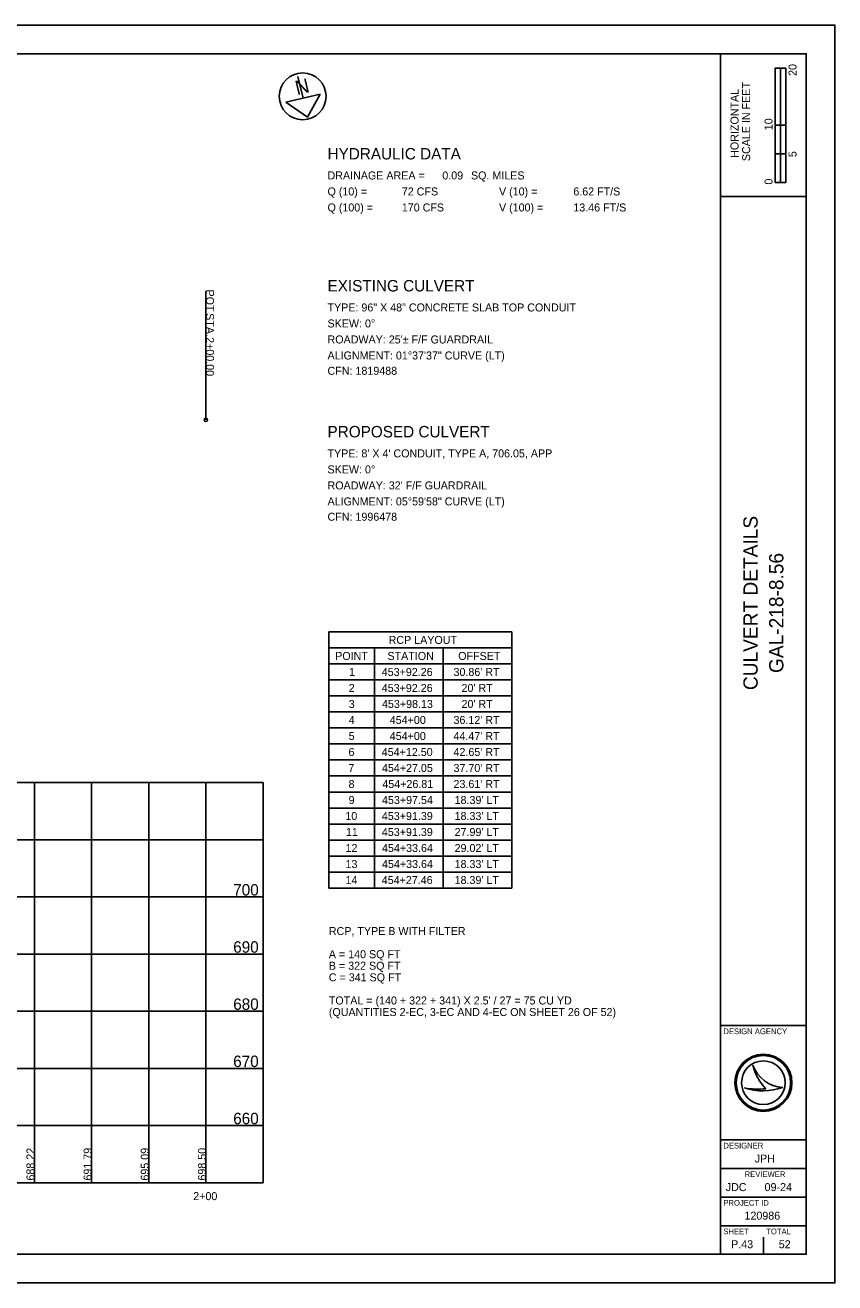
# Model space of a CAD drawing. Extents: x -1270 to 3371, y -118 to 220.
# Drawn here: x 198.4 to 340, y 0 to 220 of the extents above; entities that cross this region are included whole.
import ezdxf

# ---------------------------------------------------------------- set-up
doc = ezdxf.new("R2010")
doc.units = 0
for name, color, linetype in [('DR_P_Culvert', 7, 'Continuous'), ('DR_X_Culvert', 7, 'Continuous'), ('GE_P_Alignment', 7, 'Continuous'), ('GE_P_Alignment_100_Cardinal_Points', 7, 'Continuous'), ('GE_P_Alignment_100_Curve_Data', 7, 'Continuous'), ('PF_X_Ground_Line', 7, 'Continuous'), ('SC_Scratch1', 7, 'Continuous'), ('TX_P_1', 7, 'Continuous'), ('TX_X_1', 7, 'Continuous')]:
    doc.layers.add(name, color=color, linetype=linetype)

msp = doc.modelspace()

# ---------------------------------------------------------------- linework, layer by layer
at = {"layer": 'DR_P_Culvert'}
msp.add_line((229.98, 150.96), (229.98, 173.46), dxfattribs=at)
msp.add_circle((229.98, 150.96), 0.3, dxfattribs=at)
at = {"layer": 'DR_X_Culvert'}
msp.add_lwpolyline([(0, 0), (340, 0), (340, 220), (0, 220)], close=True, dxfattribs=at)
at = {"layer": 'GE_P_Alignment_100_Cardinal_Points'}
msp.add_circle((246.9, 207.55), 4.1, dxfattribs=at)
at = {"layer": 'GE_P_Alignment_100_Curve_Data'}
for p, q in [((246.97, 207.24), (246.07, 211)), ((249.96, 207.95), (243.98, 206.52)), ((247.77, 203.92), (249.96, 207.95)), ((243.98, 206.52), (247.77, 203.92))]:
    msp.add_line(p, q, dxfattribs=at)
msp.add_circle((246.9, 207.55), 4.1, dxfattribs=at)
at = {"layer": 'PF_X_Ground_Line'}
for p, q in [((199.98, 17.5), (199.98, 87.5)), ((209.98, 17.5), (209.98, 87.5)), ((219.98, 17.5), (219.98, 87.5)), ((229.98, 17.5), (229.98, 87.5)), ((19.98, 77.5), (239.98, 77.5)), ((19.98, 67.5), (239.98, 67.5)), ((19.98, 57.5), (239.98, 57.5)), ((19.98, 47.5), (239.98, 47.5)), ((19.98, 37.5), (239.98, 37.5)), ((19.98, 27.5), (239.98, 27.5))]:
    msp.add_line(p, q, dxfattribs=at)
at = {"layer": 'SC_Scratch1'}
for p, q in [((329.57, 192.5), (329.57, 212.5)), ((331.44, 212.5), (329.57, 212.5)), ((329.57, 202.5), (329.57, 212.5)), ((329.57, 212.5), (330.5, 212.5)), ((330.5, 212.5), (330.51, 212.5)), ((330.51, 212.5), (330.51, 202.5)), ((331.44, 212.5), (331.44, 192.5)), ((330.51, 202.5), (329.57, 202.5)), ((331.43, 202.5), (330.5, 202.5)), ((330.5, 202.5), (330.5, 197.5)), ((331.43, 197.5), (331.43, 202.5)), ((330.5, 197.5), (329.57, 197.5)), ((329.57, 197.5), (329.57, 192.5)), ((330.5, 192.5), (330.5, 197.5)), ((330.5, 197.5), (331.43, 197.5)), ((331.44, 192.5), (329.57, 192.5)), ((329.57, 192.5), (330.5, 192.5)), ((239.98, 87.5), (19.98, 87.5)), ((239.98, 17.5), (239.98, 87.5)), ((325.67, 38.1), (325.67, 38.1)), ((324.17, 34.1), (324.17, 34.1)), ((327.5, 35), (327.5, 35)), ((330.87, 34.19), (330.87, 34.19)), ((19.98, 17.5), (239.98, 17.5)), ((323.75, 6.75), (323.75, 6.75)), ((327.5, 5), (327.5, 8))]:
    msp.add_line(p, q, dxfattribs=at)
for radius in [5, 4.77, 4.77, 3.82]:
    msp.add_circle((327.5, 35), radius, dxfattribs=at)
for centre, radius, start, end in [((331.16, 39.98), 5.8, 198.9257, 198.9319), ((333.47, 39.7), 7.96, 191.6379, 191.6421), ((331.16, 39.98), 5.8, 198.9319, 267.1657), ((333.47, 39.7), 7.96, 191.6421, 226.0947), ((327.39, 43.7), 10.13, 251.4576, 290.0832), ((326.48, 46.54), 12.66, 259.4964, 259.4995), ((327.39, 43.7), 10.13, 251.4527, 251.4576), ((326.48, 46.54), 12.66, 259.4995, 276.6672)]:
    msp.add_arc(centre, radius, start, end, dxfattribs=at)
at = {"layer": 'TX_P_1'}
for p, q in [((251.48, 113.86), (283.48, 113.86)), ((251.48, 69.06), (251.48, 113.86)), ((283.48, 69.06), (283.48, 113.86)), ((251.48, 111.06), (283.48, 111.06)), ((259.48, 69.06), (259.48, 111.06)), ((271.48, 69.06), (271.48, 111.06)), ((251.48, 108.26), (283.48, 108.26)), ((251.48, 105.46), (283.48, 105.46)), ((251.48, 102.66), (283.48, 102.66)), ((251.48, 99.86), (283.48, 99.86)), ((251.48, 97.06), (283.48, 97.06)), ((251.48, 94.26), (283.48, 94.26)), ((251.48, 91.46), (283.48, 91.46)), ((251.48, 88.66), (283.48, 88.66)), ((251.48, 85.86), (283.48, 85.86)), ((251.48, 83.06), (283.48, 83.06)), ((251.48, 80.26), (283.48, 80.26)), ((251.48, 77.46), (283.48, 77.46)), ((251.48, 74.66), (283.48, 74.66)), ((251.48, 71.86), (283.48, 71.86)), ((251.48, 69.06), (283.48, 69.06))]:
    msp.add_line(p, q, dxfattribs=at)
at = {"layer": 'TX_X_1'}
for p, q in [((320, 5), (320, 215)), ((320, 190), (335, 190)), ((320, 45), (335, 45)), ((320, 25), (335, 25)), ((320, 20), (335, 20)), ((320, 15), (335, 15)), ((320, 10), (335, 10))]:
    msp.add_line(p, q, dxfattribs=at)
msp.add_lwpolyline([(15, 215), (335, 215), (335, 5), (15, 5)], close=True, dxfattribs=at)

# ---------------------------------------------------------------- texts
at = {"layer": 'DR_P_Culvert'}
for s, p in [('POT', (230, 173.75)), (' STA. ', (230, 170.14)), ('2+00.00', (230, 165.42))]:
    msp.add_text(s, height=1.4, rotation=270, dxfattribs=at).set_placement(p)
at = {"layer": 'GE_P_Alignment'}
for s, p in [('STATION', (261.74, 108.96)), ('OFFSET', (274.11, 108.96)), ('453+92.26', (260.74, 106.16)), ("30.86' RT", (273.29, 106.16)), ('453+92.26', (260.74, 103.36)), ("20' RT", (274.69, 103.36)), ('453+98.13', (260.78, 100.56)), ("20' RT", (274.69, 100.56)), ('454+00', (262.14, 97.76)), ("36.12' RT", (273.29, 97.76)), ('454+00', (262.14, 94.96)), ("44.47' RT", (273.29, 94.96)), ('454+12.50', (260.74, 92.16)), ("42.65' RT", (273.29, 92.16)), ('454+27.05', (260.77, 89.36)), ("37.70' RT", (273.29, 89.36)), ('454+26.81', (260.84, 86.56)), ("23.61' RT", (273.29, 86.56)), ('453+97.54', (260.78, 83.76)), ("18.39' LT", (273.48, 83.76)), ('453+91.39', (260.76, 80.96)), ("18.33' LT", (273.48, 80.96)), ('453+91.39', (260.76, 78.16)), ("27.99' LT", (273.48, 78.16)), ('454+33.64', (260.78, 75.36)), ("29.02' LT", (273.48, 75.36)), ('454+33.64', (260.78, 72.56)), ("18.33' LT", (273.48, 72.56)), ('454+27.46', (260.74, 69.76)), ("18.39' LT", (273.48, 69.76)), ('RCP, TYPE B WITH FILTER', (251.48, 60.84)), ('A = 140 SQ FT', (251.48, 56.79)), ('B = 322 SQ FT', (251.48, 54.77)), ('C = 341 SQ FT', (251.48, 52.74)), ("TOTAL = (140 + 322 + 341) X 2.5' / 27 = 75 CU YD", (251.48, 48.69)), ('(QUANTITIES 2-EC, 3-EC AND 4-EC ON SHEET 26 OF 52)', (251.48, 46.67))]:
    msp.add_text(s, height=1.4, dxfattribs=at).set_placement(p)
for s, p in [('688.22', (199.98, 17.89)), ('691.79', (209.98, 17.89)), ('695.09', (219.98, 17.89)), ('698.50', (229.98, 17.89))]:
    msp.add_text(s, height=1.4, rotation=90, dxfattribs=at).set_placement(p)
at = {"layer": 'GE_P_Alignment_100_Curve_Data'}
msp.add_text('N', height=2.5, rotation=193.4313, dxfattribs=at).set_placement((247.69, 210.74))
at = {"layer": 'SC_Scratch1'}
for s, height, p in [('20', 1.4, (333.3, 211.12)), ('SCALE IN FEET', 1.4, (325.18, 196.21)), ('HORIZONTAL', 1.4, (323.15, 196.79)), ('10', 1.4, (329.1, 201.62)), ('5', 1.4, (333.3, 196.91)), ('0', 1.4, (329.1, 192.11)), ('CULVERT DETAILS', 2.5, (326.5, 103.69)), ('GAL-218-8.56', 2.5, (331, 106.68))]:
    msp.add_text(s, height=height, rotation=90, dxfattribs=at).set_placement(p)
for s, height, p in [('700', 2, (234.75, 67.75)), ('690', 2, (234.75, 57.75)), ('680', 2, (234.75, 47.75)), ('DESIGN AGENCY', 1, (320.5, 43.5)), ('670', 2, (234.75, 37.75)), ('660', 2, (234.75, 27.75)), ('DESIGNER', 1, (320.5, 23.5)), ('JPH', 1.4, (325.98, 21.05)), ('REVIEWER', 1, (324.22, 18.5)), ('JDC', 1.4, (320.91, 16.05)), ('09-24', 1.4, (327.71, 16.05)), ('PROJECT ID', 1, (320.5, 13.5)), ('120986', 1.4, (324.19, 11.05)), ('SHEET', 1, (320.5, 8.5)), ('TOTAL', 1, (328, 8.5)), ('P.43', 1.4, (321.85, 6.05)), ('52', 1.4, (330.19, 6.05))]:
    msp.add_text(s, height=height, dxfattribs=at).set_placement(p)
at = {"layer": 'TX_P_1'}
for s, height, p in [('HYDRAULIC DATA', 2, (251.25, 196.51)), ('DRAINAGE AREA =', 1.4, (251.25, 193.01)), ('0.09', 1.4, (271.33, 193.01)), ('SQ. MILES', 1.4, (276.35, 193.01)), ('Q (10) =', 1.4, (251.25, 190.21)), ('72 CFS', 1.4, (264.25, 190.21)), ('V (10) =', 1.4, (281.25, 190.21)), ('6.62 FT/S', 1.4, (294.25, 190.21)), ('Q (100) =', 1.4, (251.25, 187.41)), ('170 CFS', 1.4, (264.25, 187.41)), ('V (100) =', 1.4, (281.25, 187.41)), ('13.46 FT/S', 1.4, (294.25, 187.41)), ('EXISTING CULVERT', 2, (251.25, 173.42)), ('TYPE: 96" X 48" CONCRETE SLAB TOP CONDUIT', 1.4, (251.25, 169.92)), ('SKEW: 0°', 1.4, (251.25, 167.12)), ("ROADWAY: 25'± F/F GUARDRAIL", 1.4, (251.25, 164.32)), ('ALIGNMENT: 01°37\'37" CURVE (LT)', 1.4, (251.25, 161.52)), ('CFN: 1819488', 1.4, (251.25, 158.84)), ('PROPOSED CULVERT', 2, (251.25, 147.89)), ("TYPE: 8' X 4' CONDUIT, TYPE A, 706.05, APP", 1.4, (251.25, 144.39)), ('SKEW: 0°', 1.4, (251.25, 141.59)), ("ROADWAY: 32' F/F GUARDRAIL", 1.4, (251.25, 138.79)), ('ALIGNMENT: 05°59\'58" CURVE (LT)', 1.4, (251.25, 135.99)), ('CFN: 1996478', 1.4, (251.25, 133.31)), ('RCP LAYOUT', 1.4, (261.94, 111.76)), ('POINT', 1.4, (252.59, 108.96)), ('1', 1.4, (255.02, 106.16)), ('2', 1.4, (254.96, 103.36)), ('3', 1.4, (254.96, 100.56)), ('4', 1.4, (254.96, 97.76)), ('5', 1.4, (254.95, 94.96)), ('6', 1.4, (254.92, 92.16)), ('7', 1.4, (254.89, 89.36)), ('8', 1.4, (254.93, 86.56)), ('9', 1.4, (254.94, 83.76)), ('10', 1.4, (254.37, 80.96)), ('11', 1.4, (254.46, 78.16)), ('12', 1.4, (254.4, 75.36)), ('13', 1.4, (254.4, 72.56)), ('14', 1.4, (254.4, 69.76)), ('2+00', 1.4, (227.76, 14.47))]:
    msp.add_text(s, height=height, dxfattribs=at).set_placement(p)

doc.saveas('drawing.dxf')
